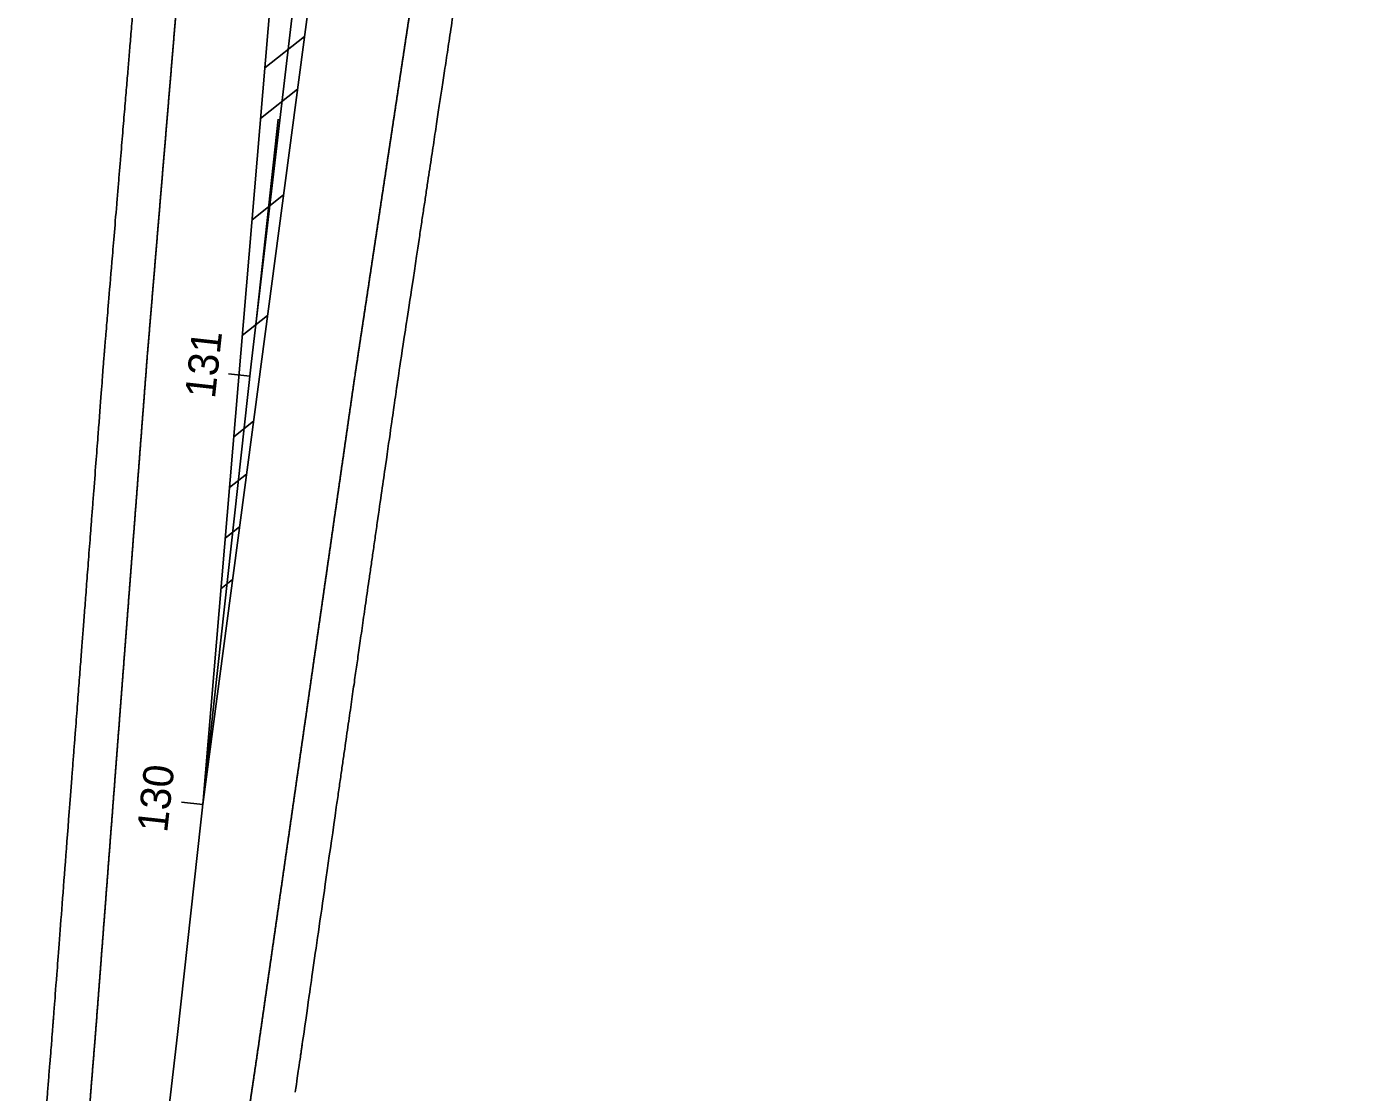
# Model space of a CAD drawing. Extents: x 2318076 to 2324211, y 613525 to 629939.
# Drawn here: x 2320467.1 to 2320778.2, y 627507.5 to 627754.8 of the extents above; entities that cross this region are included whole.
import ezdxf

# ---------------------------------------------------------------- set-up
doc = ezdxf.new("R2010")
doc.units = 0
for name, color, linetype in [('GE_P_CL_50', 7, 'Continuous'), ('PM_P_CL_Double_Solid', 7, 'Continuous'), ('PM_P_Transverse_Line', 7, 'Continuous'), ('PV_P_EOP', 7, 'Continuous'), ('PV_P_Shoulder', 7, 'Continuous')]:
    doc.layers.add(name, color=color, linetype=linetype)

msp = doc.modelspace()

# ---------------------------------------------------------------- linework, layer by layer
at = {"layer": 'GE_P_CL_50'}
for p, q in [((2320518.91, 627673.67), (2320513.94, 627674.22)), ((2320507.98, 627574.27), (2320503.01, 627574.82))]:
    msp.add_line(p, q, dxfattribs=at)
msp.add_lwpolyline([(2320485.22, 627375.57), (2320502.11, 627520.92), (2320519.22, 627676.47), (2320531.82, 627783.89), (2320546.8, 627927.12), (2320554.45, 627991.34), (2320572.51, 628138.41), (2320649.52, 628804.84), (2320678.77, 629064.5), (2320690.76, 629163.78), (2320713.75, 629362.45), (2320725.26, 629461.78), (2320736.97, 629561.09), (2320748.4, 629660.43), (2320759.09, 629759.86), (2320769.62, 629859.3), (2320777.51, 629931.12), (2320778.25, 629937.84)], dxfattribs=at)
at = {"layer": 'PM_P_CL_Double_Solid'}
for q in [(2320526.13, 627789.71), (2320536.46, 627789.06)]:
    msp.add_line((2320507.98, 627574.27), q, dxfattribs=at)
at = {"layer": 'PM_P_Transverse_Line'}
for p, q in [((2320531.62, 627752.56), (2320522.38, 627745.25)), ((2320529.99, 627740.3), (2320521.39, 627733.49)), ((2320520.29, 627685.6), (2320525.47, 627733.32)), ((2320526.74, 627715.79), (2320519.41, 627709.99)), ((2320523.03, 627687.77), (2320517.15, 627683.11)), ((2320523.03, 627687.77), (2320517.15, 627683.11)), ((2320519.78, 627663.26), (2320515.17, 627659.61)), ((2320518.15, 627651), (2320514.18, 627647.85)), ((2320516.53, 627638.75), (2320513.19, 627636.1)), ((2320516.53, 627638.75), (2320513.5, 627636.35)), ((2320514.9, 627626.49), (2320512.2, 627624.35)), ((2320514.9, 627626.49), (2320512.2, 627624.35)), ((2320512.39, 627613.53), (2320512.15, 627613.34)), ((2320509.9, 627589.62), (2320509.38, 627589.21))]:
    msp.add_line(p, q, dxfattribs=at)
at = {"layer": 'PV_P_EOP'}
for points in [[(2320497.98, 627712.83), (2320498.05, 627713.73), (2320498.13, 627714.63), (2320498.2, 627715.53), (2320498.28, 627716.43), (2320498.35, 627717.32), (2320498.43, 627718.22), (2320498.5, 627719.12), (2320498.58, 627720.02), (2320498.65, 627720.92), (2320498.73, 627721.81), (2320498.8, 627722.71), (2320498.88, 627723.61), (2320498.95, 627724.51), (2320499.03, 627725.41), (2320499.11, 627726.31), (2320499.18, 627727.2), (2320499.26, 627728.1), (2320499.33, 627729), (2320499.41, 627729.9), (2320499.48, 627730.8), (2320499.56, 627731.7), (2320499.63, 627732.59), (2320499.71, 627733.49), (2320499.78, 627734.39), (2320499.86, 627735.29), (2320499.93, 627736.19), (2320500.01, 627737.09), (2320500.08, 627737.98), (2320500.16, 627738.88), (2320500.23, 627739.78), (2320500.31, 627740.68), (2320500.38, 627741.58), (2320500.46, 627742.48), (2320500.53, 627743.37), (2320500.61, 627744.27), (2320500.68, 627745.17), (2320500.76, 627746.07), (2320500.83, 627746.97), (2320500.91, 627747.86), (2320500.98, 627748.76), (2320501.06, 627749.66), (2320501.13, 627750.56), (2320501.21, 627751.46), (2320501.28, 627752.36), (2320501.36, 627753.25), (2320501.43, 627754.15), (2320501.51, 627755.05), (2320501.58, 627755.95), (2320501.66, 627756.85), (2320501.73, 627757.75), (2320501.81, 627758.64), (2320501.88, 627759.54), (2320501.96, 627760.44), (2320502.03, 627761.34), (2320502.11, 627762.24), (2320502.18, 627763.14), (2320502.26, 627764.03), (2320502.33, 627764.93), (2320502.41, 627765.83), (2320502.48, 627766.73), (2320502.56, 627767.63), (2320502.63, 627768.53), (2320502.71, 627769.42), (2320502.78, 627770.32), (2320502.86, 627771.22), (2320502.93, 627772.12), (2320503.01, 627773.02), (2320503.08, 627773.91), (2320503.16, 627774.81), (2320503.23, 627775.71), (2320503.31, 627776.61), (2320503.38, 627777.51), (2320503.46, 627778.41), (2320503.53, 627779.3)], [(2320548.3, 627706.93), (2320548.44, 627707.82), (2320548.57, 627708.72), (2320548.71, 627709.61), (2320548.84, 627710.5), (2320548.97, 627711.39), (2320549.11, 627712.28), (2320549.24, 627713.17), (2320549.38, 627714.06), (2320549.51, 627714.95), (2320549.65, 627715.85), (2320549.78, 627716.74), (2320549.92, 627717.63), (2320550.05, 627718.52), (2320550.19, 627719.41), (2320550.32, 627720.3), (2320550.46, 627721.19), (2320550.59, 627722.08), (2320550.73, 627722.98), (2320550.86, 627723.87), (2320551, 627724.76), (2320551.13, 627725.65), (2320551.26, 627726.54), (2320551.4, 627727.43), (2320551.53, 627728.32), (2320551.67, 627729.22), (2320551.8, 627730.11), (2320551.94, 627731), (2320552.07, 627731.89), (2320552.21, 627732.78), (2320552.34, 627733.67), (2320552.48, 627734.56), (2320552.61, 627735.45), (2320552.75, 627736.35), (2320552.88, 627737.24), (2320553.02, 627738.13), (2320553.15, 627739.02), (2320553.29, 627739.91), (2320553.42, 627740.8), (2320553.56, 627741.69), (2320553.69, 627742.58), (2320553.82, 627743.48), (2320553.96, 627744.37), (2320554.09, 627745.26), (2320554.23, 627746.15), (2320554.36, 627747.04), (2320554.5, 627747.93), (2320554.63, 627748.82), (2320554.77, 627749.71), (2320554.9, 627750.61), (2320555.04, 627751.5), (2320555.17, 627752.39), (2320555.31, 627753.28), (2320555.44, 627754.17), (2320555.58, 627755.06), (2320555.71, 627755.95), (2320555.85, 627756.84), (2320555.98, 627757.74), (2320556.11, 627758.63), (2320556.25, 627759.52), (2320556.38, 627760.41), (2320556.52, 627761.3), (2320556.65, 627762.19), (2320556.79, 627763.08), (2320556.92, 627763.97), (2320557.06, 627764.87), (2320557.19, 627765.76), (2320557.33, 627766.65), (2320557.46, 627767.54), (2320557.6, 627768.43), (2320557.73, 627769.32), (2320557.87, 627770.21), (2320558, 627771.11), (2320558.14, 627772), (2320558.27, 627772.89)], [(2320492.64, 627646.17), (2320492.71, 627647.07), (2320492.78, 627647.97), (2320492.84, 627648.87), (2320492.91, 627649.77), (2320492.98, 627650.66), (2320493.05, 627651.56), (2320493.12, 627652.46), (2320493.19, 627653.36), (2320493.26, 627654.26), (2320493.33, 627655.16), (2320493.39, 627656.06), (2320493.46, 627656.96), (2320493.53, 627657.86), (2320493.6, 627658.75), (2320493.67, 627659.65), (2320493.74, 627660.55), (2320493.81, 627661.45), (2320493.87, 627662.35), (2320493.94, 627663.25), (2320494.01, 627664.15), (2320494.08, 627665.05), (2320494.15, 627665.94), (2320494.22, 627666.84), (2320494.29, 627667.74), (2320494.36, 627668.64), (2320494.42, 627669.54), (2320494.49, 627670.44), (2320494.56, 627671.34), (2320494.63, 627672.24), (2320494.7, 627673.13), (2320494.77, 627674.03), (2320494.84, 627674.93), (2320494.91, 627675.83), (2320494.97, 627676.73), (2320495.04, 627677.63), (2320495.11, 627678.53), (2320495.2, 627679.6), (2320495.28, 627680.49), (2320495.35, 627681.39), (2320495.43, 627682.29), (2320495.5, 627683.19), (2320495.58, 627684.09), (2320495.65, 627684.99), (2320495.73, 627685.88), (2320495.8, 627686.78), (2320495.88, 627687.68), (2320495.95, 627688.58), (2320496.03, 627689.48), (2320496.1, 627690.38), (2320496.18, 627691.27), (2320496.25, 627692.17), (2320496.33, 627693.07), (2320496.4, 627693.97), (2320496.48, 627694.87), (2320496.55, 627695.77), (2320496.63, 627696.66), (2320496.7, 627697.56), (2320496.78, 627698.46), (2320496.85, 627699.36), (2320496.93, 627700.26), (2320497, 627701.15), (2320497.08, 627702.05), (2320497.15, 627702.95), (2320497.23, 627703.85), (2320497.3, 627704.75), (2320497.38, 627705.65), (2320497.45, 627706.54), (2320497.53, 627707.44), (2320497.6, 627708.34), (2320497.68, 627709.24), (2320497.75, 627710.14), (2320497.83, 627711.04), (2320497.9, 627711.93), (2320497.98, 627712.83)], [(2320538.58, 627641.12), (2320538.71, 627642.01), (2320538.84, 627642.9), (2320538.97, 627643.79), (2320539.1, 627644.68), (2320539.23, 627645.58), (2320539.35, 627646.47), (2320539.48, 627647.36), (2320539.61, 627648.25), (2320539.74, 627649.14), (2320539.87, 627650.04), (2320540, 627650.93), (2320540.12, 627651.82), (2320540.25, 627652.71), (2320540.38, 627653.61), (2320540.51, 627654.5), (2320540.64, 627655.39), (2320540.77, 627656.28), (2320540.89, 627657.17), (2320541.02, 627658.07), (2320541.15, 627658.96), (2320541.28, 627659.85), (2320541.41, 627660.74), (2320541.54, 627661.64), (2320541.66, 627662.53), (2320541.79, 627663.42), (2320541.92, 627664.31), (2320542.05, 627665.2), (2320542.18, 627666.1), (2320542.31, 627666.99), (2320542.44, 627667.88), (2320542.56, 627668.77), (2320542.69, 627669.67), (2320542.82, 627670.56), (2320542.95, 627671.45), (2320543.08, 627672.34), (2320543.21, 627673.23), (2320543.32, 627673.96), (2320543.45, 627674.85), (2320543.59, 627675.74), (2320543.72, 627676.63), (2320543.86, 627677.52), (2320543.99, 627678.41), (2320544.12, 627679.3), (2320544.26, 627680.19), (2320544.39, 627681.09), (2320544.53, 627681.98), (2320544.66, 627682.87), (2320544.8, 627683.76), (2320544.93, 627684.65), (2320545.07, 627685.54), (2320545.2, 627686.43), (2320545.34, 627687.33), (2320545.47, 627688.22), (2320545.61, 627689.11), (2320545.74, 627690), (2320545.88, 627690.89), (2320546.01, 627691.78), (2320546.15, 627692.67), (2320546.28, 627693.56), (2320546.42, 627694.46), (2320546.55, 627695.35), (2320546.68, 627696.24), (2320546.82, 627697.13), (2320546.95, 627698.02), (2320547.09, 627698.91), (2320547.22, 627699.8), (2320547.36, 627700.69), (2320547.49, 627701.59), (2320547.63, 627702.48), (2320547.76, 627703.37), (2320547.9, 627704.26), (2320548.03, 627705.15), (2320548.17, 627706.04), (2320548.3, 627706.93)], [(2320487.56, 627579.66), (2320487.62, 627580.56), (2320487.69, 627581.46), (2320487.76, 627582.36), (2320487.83, 627583.26), (2320487.9, 627584.16), (2320487.97, 627585.05), (2320488.04, 627585.95), (2320488.1, 627586.85), (2320488.17, 627587.75), (2320488.24, 627588.65), (2320488.31, 627589.55), (2320488.38, 627590.45), (2320488.45, 627591.35), (2320488.52, 627592.24), (2320488.59, 627593.14), (2320488.65, 627594.04), (2320488.72, 627594.94), (2320488.79, 627595.84), (2320488.86, 627596.74), (2320488.93, 627597.64), (2320489, 627598.54), (2320489.07, 627599.43), (2320489.14, 627600.33), (2320489.2, 627601.23), (2320489.27, 627602.13), (2320489.34, 627603.03), (2320489.41, 627603.93), (2320489.48, 627604.83), (2320489.55, 627605.73), (2320489.62, 627606.62), (2320489.68, 627607.52), (2320489.75, 627608.42), (2320489.82, 627609.32), (2320489.89, 627610.22), (2320489.96, 627611.12), (2320490.03, 627612.02), (2320490.1, 627612.92), (2320490.17, 627613.81), (2320490.23, 627614.71), (2320490.3, 627615.61), (2320490.37, 627616.51), (2320490.44, 627617.41), (2320490.51, 627618.31), (2320490.58, 627619.21), (2320490.65, 627620.11), (2320490.72, 627621.01), (2320490.78, 627621.9), (2320490.85, 627622.8), (2320490.92, 627623.7), (2320490.99, 627624.6), (2320491.06, 627625.5), (2320491.13, 627626.4), (2320491.2, 627627.3), (2320491.26, 627628.2), (2320491.33, 627629.09), (2320491.4, 627629.99), (2320491.47, 627630.89), (2320491.54, 627631.79), (2320491.61, 627632.69), (2320491.68, 627633.59), (2320491.75, 627634.49), (2320491.81, 627635.39), (2320491.88, 627636.28), (2320491.95, 627637.18), (2320492.02, 627638.08), (2320492.09, 627638.98), (2320492.16, 627639.88), (2320492.23, 627640.78), (2320492.29, 627641.68), (2320492.36, 627642.58), (2320492.43, 627643.47), (2320492.5, 627644.37), (2320492.57, 627645.27), (2320492.64, 627646.17)], [(2320529.08, 627575.09), (2320529.21, 627575.98), (2320529.34, 627576.88), (2320529.47, 627577.77), (2320529.6, 627578.66), (2320529.72, 627579.55), (2320529.85, 627580.44), (2320529.98, 627581.34), (2320530.11, 627582.23), (2320530.24, 627583.12), (2320530.37, 627584.01), (2320530.49, 627584.91), (2320530.62, 627585.8), (2320530.75, 627586.69), (2320530.88, 627587.58), (2320531.01, 627588.47), (2320531.14, 627589.37), (2320531.27, 627590.26), (2320531.39, 627591.15), (2320531.52, 627592.04), (2320531.65, 627592.94), (2320531.78, 627593.83), (2320531.91, 627594.72), (2320532.04, 627595.61), (2320532.16, 627596.5), (2320532.29, 627597.4), (2320532.42, 627598.29), (2320532.55, 627599.18), (2320532.68, 627600.07), (2320532.81, 627600.97), (2320532.93, 627601.86), (2320533.06, 627602.75), (2320533.19, 627603.64), (2320533.32, 627604.53), (2320533.45, 627605.43), (2320533.58, 627606.32), (2320533.7, 627607.21), (2320533.83, 627608.1), (2320533.96, 627609), (2320534.09, 627609.89), (2320534.22, 627610.78), (2320534.35, 627611.67), (2320534.47, 627612.56), (2320534.6, 627613.46), (2320534.73, 627614.35), (2320534.86, 627615.24), (2320534.99, 627616.13), (2320535.12, 627617.03), (2320535.25, 627617.92), (2320535.37, 627618.81), (2320535.5, 627619.7), (2320535.63, 627620.59), (2320535.76, 627621.49), (2320535.89, 627622.38), (2320536.02, 627623.27), (2320536.14, 627624.16), (2320536.27, 627625.06), (2320536.4, 627625.95), (2320536.53, 627626.84), (2320536.66, 627627.73), (2320536.79, 627628.62), (2320536.91, 627629.52), (2320537.04, 627630.41), (2320537.17, 627631.3), (2320537.3, 627632.19), (2320537.43, 627633.09), (2320537.56, 627633.98), (2320537.68, 627634.87), (2320537.81, 627635.76), (2320537.94, 627636.65), (2320538.07, 627637.55), (2320538.2, 627638.44), (2320538.33, 627639.33), (2320538.45, 627640.22), (2320538.58, 627641.12)], [(2320482.44, 627513.23), (2320482.51, 627514.12), (2320482.59, 627515.02), (2320482.66, 627515.92), (2320482.73, 627516.82), (2320482.8, 627517.72), (2320482.88, 627518.62), (2320482.95, 627519.52), (2320483.02, 627520.41), (2320483.09, 627521.31), (2320483.16, 627522.21), (2320483.23, 627523.04), (2320483.3, 627523.94), (2320483.37, 627524.84), (2320483.43, 627525.73), (2320483.5, 627526.63), (2320483.57, 627527.53), (2320483.64, 627528.43), (2320483.71, 627529.33), (2320483.78, 627530.23), (2320483.85, 627531.13), (2320483.91, 627532.03), (2320483.98, 627532.92), (2320484.05, 627533.82), (2320484.12, 627534.72), (2320484.19, 627535.62), (2320484.26, 627536.52), (2320484.33, 627537.42), (2320484.4, 627538.32), (2320484.46, 627539.22), (2320484.53, 627540.11), (2320484.6, 627541.01), (2320484.67, 627541.91), (2320484.74, 627542.81), (2320484.81, 627543.71), (2320484.88, 627544.61), (2320484.94, 627545.51), (2320485.01, 627546.41), (2320485.08, 627547.31), (2320485.15, 627548.2), (2320485.22, 627549.1), (2320485.29, 627550), (2320485.36, 627550.9), (2320485.43, 627551.8), (2320485.49, 627552.7), (2320485.56, 627553.6), (2320485.63, 627554.5), (2320485.7, 627555.39), (2320485.77, 627556.29), (2320485.84, 627557.19), (2320485.91, 627558.09), (2320485.98, 627558.99), (2320486.04, 627559.89), (2320486.11, 627560.79), (2320486.18, 627561.69), (2320486.25, 627562.58), (2320486.32, 627563.48), (2320486.39, 627564.38), (2320486.46, 627565.28), (2320486.52, 627566.18), (2320486.59, 627567.08), (2320486.66, 627567.98), (2320486.73, 627568.88), (2320486.8, 627569.77), (2320486.87, 627570.67), (2320486.94, 627571.57), (2320487.01, 627572.47), (2320487.07, 627573.37), (2320487.14, 627574.27), (2320487.21, 627575.17), (2320487.28, 627576.07), (2320487.35, 627576.96), (2320487.42, 627577.86), (2320487.49, 627578.76), (2320487.56, 627579.66)], [(2320519.54, 627509), (2320519.67, 627509.89), (2320519.8, 627510.78), (2320519.93, 627511.68), (2320520.06, 627512.57), (2320520.2, 627513.46), (2320520.33, 627514.35), (2320520.46, 627515.24), (2320520.59, 627516.14), (2320520.72, 627517.03), (2320520.85, 627517.92), (2320520.99, 627518.88), (2320521.12, 627519.77), (2320521.25, 627520.67), (2320521.38, 627521.56), (2320521.51, 627522.45), (2320521.64, 627523.34), (2320521.76, 627524.24), (2320521.89, 627525.13), (2320522.02, 627526.02), (2320522.15, 627526.91), (2320522.28, 627527.8), (2320522.41, 627528.7), (2320522.53, 627529.59), (2320522.66, 627530.48), (2320522.79, 627531.37), (2320522.92, 627532.27), (2320523.05, 627533.16), (2320523.18, 627534.05), (2320523.3, 627534.94), (2320523.43, 627535.83), (2320523.56, 627536.73), (2320523.69, 627537.62), (2320523.82, 627538.51), (2320523.95, 627539.4), (2320524.08, 627540.3), (2320524.2, 627541.19), (2320524.33, 627542.08), (2320524.46, 627542.97), (2320524.59, 627543.86), (2320524.72, 627544.76), (2320524.85, 627545.65), (2320524.97, 627546.54), (2320525.1, 627547.43), (2320525.23, 627548.33), (2320525.36, 627549.22), (2320525.49, 627550.11), (2320525.62, 627551), (2320525.74, 627551.89), (2320525.87, 627552.79), (2320526, 627553.68), (2320526.13, 627554.57), (2320526.26, 627555.46), (2320526.39, 627556.36), (2320526.51, 627557.25), (2320526.64, 627558.14), (2320526.77, 627559.03), (2320526.9, 627559.92), (2320527.03, 627560.82), (2320527.16, 627561.71), (2320527.28, 627562.6), (2320527.41, 627563.49), (2320527.54, 627564.38), (2320527.67, 627565.28), (2320527.8, 627566.17), (2320527.93, 627567.06), (2320528.06, 627567.95), (2320528.18, 627568.85), (2320528.31, 627569.74), (2320528.44, 627570.63), (2320528.57, 627571.52), (2320528.7, 627572.41), (2320528.83, 627573.31), (2320528.95, 627574.2), (2320529.08, 627575.09)], [(2320477.11, 627446.74), (2320477.18, 627447.63), (2320477.25, 627448.53), (2320477.32, 627449.43), (2320477.39, 627450.33), (2320477.47, 627451.23), (2320477.54, 627452.13), (2320477.61, 627453.03), (2320477.68, 627453.92), (2320477.76, 627454.82), (2320477.83, 627455.72), (2320477.9, 627456.62), (2320477.97, 627457.52), (2320478.04, 627458.42), (2320478.12, 627459.32), (2320478.19, 627460.21), (2320478.26, 627461.11), (2320478.33, 627462.01), (2320478.4, 627462.91), (2320478.48, 627463.81), (2320478.55, 627464.71), (2320478.62, 627465.61), (2320478.69, 627466.5), (2320478.76, 627467.4), (2320478.84, 627468.3), (2320478.91, 627469.2), (2320478.98, 627470.1), (2320479.05, 627471), (2320479.13, 627471.89), (2320479.2, 627472.79), (2320479.27, 627473.69), (2320479.34, 627474.59), (2320479.41, 627475.49), (2320479.49, 627476.39), (2320479.56, 627477.29), (2320479.63, 627478.18), (2320479.7, 627479.08), (2320479.77, 627479.98), (2320479.85, 627480.88), (2320479.92, 627481.78), (2320479.99, 627482.68), (2320480.06, 627483.58), (2320480.13, 627484.47), (2320480.21, 627485.37), (2320480.28, 627486.27), (2320480.35, 627487.17), (2320480.42, 627488.07), (2320480.5, 627488.97), (2320480.57, 627489.87), (2320480.64, 627490.76), (2320480.71, 627491.66), (2320480.78, 627492.56), (2320480.86, 627493.46), (2320480.93, 627494.36), (2320481, 627495.26), (2320481.07, 627496.15), (2320481.14, 627497.05), (2320481.22, 627497.95), (2320481.29, 627498.85), (2320481.36, 627499.75), (2320481.43, 627500.65), (2320481.51, 627501.55), (2320481.58, 627502.44), (2320481.65, 627503.34), (2320481.72, 627504.24), (2320481.79, 627505.14), (2320481.87, 627506.04), (2320481.94, 627506.94), (2320482.01, 627507.84), (2320482.08, 627508.73), (2320482.15, 627509.63), (2320482.23, 627510.53), (2320482.3, 627511.43), (2320482.37, 627512.33), (2320482.44, 627513.23)], [(2320509.78, 627443.01), (2320509.92, 627443.91), (2320510.05, 627444.8), (2320510.18, 627445.69), (2320510.31, 627446.58), (2320510.44, 627447.47), (2320510.57, 627448.36), (2320510.71, 627449.26), (2320510.84, 627450.15), (2320510.97, 627451.04), (2320511.1, 627451.93), (2320511.23, 627452.82), (2320511.37, 627453.72), (2320511.5, 627454.61), (2320511.63, 627455.5), (2320511.76, 627456.39), (2320511.89, 627457.28), (2320512.02, 627458.17), (2320512.16, 627459.07), (2320512.29, 627459.96), (2320512.42, 627460.85), (2320512.55, 627461.74), (2320512.68, 627462.63), (2320512.81, 627463.52), (2320512.95, 627464.42), (2320513.08, 627465.31), (2320513.21, 627466.2), (2320513.34, 627467.09), (2320513.47, 627467.98), (2320513.61, 627468.87), (2320513.74, 627469.77), (2320513.87, 627470.66), (2320514, 627471.55), (2320514.13, 627472.44), (2320514.26, 627473.33), (2320514.4, 627474.22), (2320514.53, 627475.12), (2320514.66, 627476.01), (2320514.79, 627476.9), (2320514.92, 627477.79), (2320515.06, 627478.68), (2320515.19, 627479.57), (2320515.32, 627480.47), (2320515.45, 627481.36), (2320515.58, 627482.25), (2320515.71, 627483.14), (2320515.85, 627484.03), (2320515.98, 627484.93), (2320516.11, 627485.82), (2320516.24, 627486.71), (2320516.37, 627487.6), (2320516.5, 627488.49), (2320516.64, 627489.38), (2320516.77, 627490.28), (2320516.9, 627491.17), (2320517.03, 627492.06), (2320517.16, 627492.95), (2320517.3, 627493.84), (2320517.43, 627494.73), (2320517.56, 627495.63), (2320517.69, 627496.52), (2320517.82, 627497.41), (2320517.95, 627498.3), (2320518.09, 627499.19), (2320518.22, 627500.08), (2320518.35, 627500.98), (2320518.48, 627501.87), (2320518.61, 627502.76), (2320518.75, 627503.65), (2320518.88, 627504.54), (2320519.01, 627505.43), (2320519.14, 627506.33), (2320519.27, 627507.22), (2320519.4, 627508.11), (2320519.54, 627509)]]:
    msp.add_spline(points, degree=3, dxfattribs=at)
at = {"layer": 'PV_P_Shoulder'}
for points, degree in [([(2320488.01, 627713.67), (2320489.87, 627735.82), (2320491.72, 627757.98), (2320493.57, 627780.14)], 2), ([(2320558.19, 627705.44), (2320561.51, 627727.42), (2320564.83, 627749.41), (2320568.16, 627771.39)], 2), ([(2320482.67, 627646.93), (2320483.09, 627652.49), (2320483.73, 627660.82), (2320484.47, 627670.55), (2320484.84, 627675.41), (2320485.03, 627677.84), (2320485.11, 627678.9), (2320485.14, 627679.25), (2320485.14, 627679.27), (2320485.14, 627679.28), (2320485.14, 627679.33), (2320485.15, 627679.41), (2320485.16, 627679.49), (2320485.17, 627679.65), (2320485.18, 627679.75), (2320485.2, 627680.04), (2320485.22, 627680.21), (2320485.23, 627680.38), (2320485.23, 627680.4), (2320485.24, 627680.42), (2320485.24, 627680.43), (2320485.24, 627680.44), (2320485.24, 627680.45), (2320485.24, 627680.51), (2320485.25, 627680.65), (2320485.28, 627680.95), (2320485.33, 627681.56), (2320485.43, 627682.77), (2320485.64, 627685.2), (2320486.04, 627690.06), (2320486.85, 627699.78), (2320487.55, 627708.11), (2320488.01, 627713.67)], 3), ([(2320548.48, 627639.69), (2320549.27, 627645.18), (2320550.46, 627653.41), (2320551.84, 627663.01), (2320552.53, 627667.82), (2320552.87, 627670.22), (2320553.03, 627671.29), (2320553.09, 627671.7), (2320553.1, 627671.77), (2320553.1, 627671.79), (2320553.1, 627671.8), (2320553.1, 627671.81), (2320553.1, 627671.82), (2320553.11, 627671.85), (2320553.12, 627671.91), (2320553.14, 627672.05), (2320553.15, 627672.14), (2320553.18, 627672.29), (2320553.19, 627672.34), (2320553.2, 627672.41), (2320553.2, 627672.43), (2320553.2, 627672.45), (2320553.2, 627672.46), (2320553.21, 627672.47), (2320553.21, 627672.5), (2320554.87, 627683.49), (2320556.53, 627694.47), (2320558.19, 627705.44)], 3), ([(2320477.58, 627580.42), (2320479.28, 627602.59), (2320480.97, 627624.76), (2320482.67, 627646.93)], 2), ([(2320538.98, 627573.67), (2320542.15, 627595.68), (2320545.31, 627617.68), (2320548.48, 627639.69)], 2), ([(2320472.47, 627514.03), (2320472.7, 627516.81), (2320472.93, 627519.57), (2320473.17, 627522.65), (2320473.2, 627523.08), (2320473.23, 627523.51), (2320473.25, 627523.68), (2320473.25, 627523.76), (2320473.27, 627524.02), (2320473.34, 627524.89), (2320473.51, 627527.13), (2320474.09, 627534.75), (2320475.47, 627552.74), (2320476.74, 627569.35), (2320477.58, 627580.42)], 3), ([(2320529.43, 627507.54), (2320529.83, 627510.28), (2320530.25, 627513.03), (2320530.7, 627516.16), (2320530.78, 627516.68), (2320530.86, 627517.21), (2320530.91, 627517.56), (2320530.93, 627517.73), (2320531.05, 627518.59), (2320531.35, 627520.65), (2320532.44, 627528.23), (2320535.02, 627546.13), (2320537.4, 627562.65), (2320538.98, 627573.67)], 3), ([(2320467.14, 627447.54), (2320468.92, 627469.7), (2320470.7, 627491.86), (2320472.47, 627514.03)], 2)]:
    msp.add_open_spline(points, degree=degree, dxfattribs=at)

# ---------------------------------------------------------------- texts
at = {"layer": 'GE_P_CL_50'}
for s, p in [('131', (2320510.78, 627668.33)), ('130', (2320499.7, 627567.61))]:
    msp.add_text(s, height=7, rotation=83.7204, dxfattribs=at).set_placement(p)

doc.saveas('drawing.dxf')
